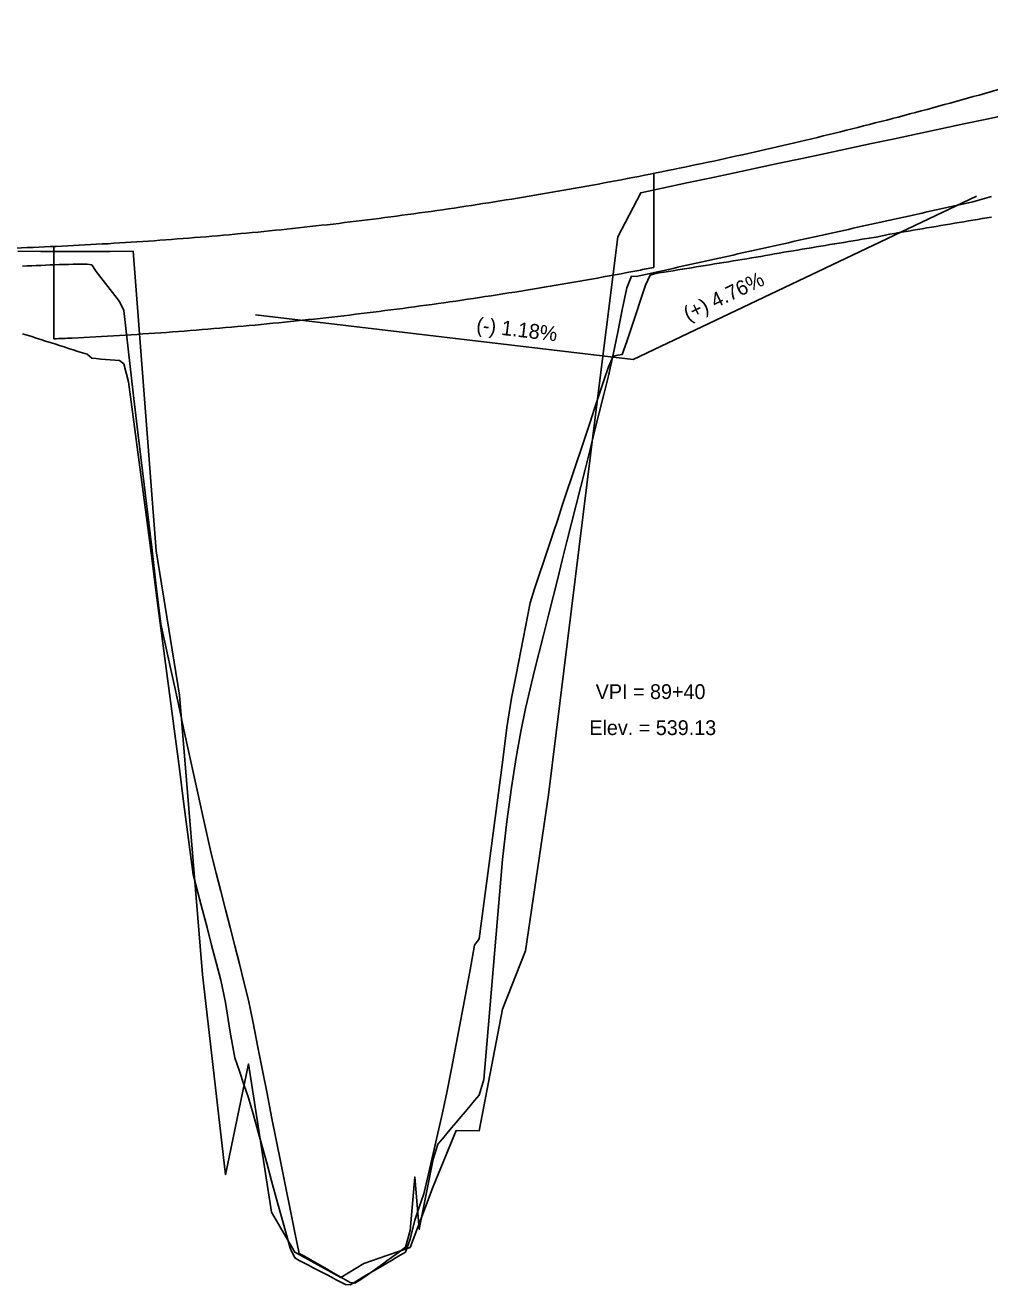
# Model space of a CAD drawing. Extents: x 1733822 to 1737718, y 1214897 to 1219897.
# Drawn here: x 1735400.6 to 1735609.6, y 1218087.6 to 1218360.6 of the extents above; entities that cross this region are included whole.
import ezdxf

# ---------------------------------------------------------------- set-up
doc = ezdxf.new("R2010")
doc.units = 0
for name, color, linetype in [('RD_DDB_GradeTX', 7, 'Continuous'), ('RD_DDB_Profile_EX', 7, 'Continuous'), ('RD_DDB_Profile_Lbl', 7, 'Continuous'), ('RD_DDB_Profile_PR', 7, 'Continuous'), ('RD_PD_Bridge', 7, 'Continuous'), ('RD_Sketch1', 7, 'Continuous'), ('RD_Sketch2', 7, 'Continuous')]:
    doc.layers.add(name, color=color, linetype=linetype)

msp = doc.modelspace()

# ---------------------------------------------------------------- linework, layer by layer
at = {"layer": 'RD_DDB_GradeTX'}
for p in [(1735606.71, 1218323.5), (1735450.48, 1218297.76)]:
    msp.add_line(p, (1735532.31, 1218288.09), dxfattribs=at)
at = {"layer": 'RD_DDB_Profile_EX'}
for points in [[(1735413.97, 1218311.54), (1735418.97, 1218311.53), (1735423.97, 1218311.57), (1735428.97, 1218246.61), (1735433.97, 1218215.39), (1735438.97, 1218154.8), (1735443.97, 1218111.43), (1735448.97, 1218135.45), (1735453.97, 1218103.33), (1735458.97, 1218094.65), (1735463.97, 1218091.91), (1735468.97, 1218089.16), (1735473.97, 1218092.22), (1735478.97, 1218093.96), (1735483.97, 1218095.69), (1735488.97, 1218108.91), (1735493.97, 1218121.02), (1735498.97, 1218120.99), (1735503.97, 1218147.3), (1735508.97, 1218159.95), (1735513.97, 1218193.75), (1735518.97, 1218234.06), (1735523.97, 1218274.37), (1735528.97, 1218314.68), (1735533.97, 1218324.23), (1735538.97, 1218325.29), (1735543.97, 1218326.36), (1735548.97, 1218327.42), (1735553.97, 1218328.49), (1735558.97, 1218329.55), (1735563.97, 1218330.62), (1735568.97, 1218331.69), (1735573.97, 1218332.75), (1735578.97, 1218333.82), (1735583.97, 1218334.88), (1735588.97, 1218335.95), (1735593.97, 1218337.02), (1735598.97, 1218338.08), (1735603.97, 1218339.15), (1735608.97, 1218340.21), (1735613.97, 1218341.28)], [(1735398.97, 1218311.55), (1735403.97, 1218311.54), (1735408.97, 1218311.54), (1735413.97, 1218311.54)]]:
    msp.add_lwpolyline(points, dxfattribs=at)
at = {"layer": 'RD_DDB_Profile_PR'}
msp.add_spline([(1735269.77, 1218317.64), (1735279.77, 1218316.52), (1735289.77, 1218315.51), (1735299.77, 1218314.63), (1735309.77, 1218313.86), (1735319.77, 1218313.22), (1735329.77, 1218312.69), (1735339.77, 1218312.28), (1735349.77, 1218311.99), (1735359.77, 1218311.81), (1735369.77, 1218311.76), (1735379.77, 1218311.83), (1735389.77, 1218312.01), (1735399.77, 1218312.31), (1735409.77, 1218312.74), (1735419.77, 1218313.28), (1735429.77, 1218313.94), (1735439.77, 1218314.72), (1735449.77, 1218315.61), (1735459.77, 1218316.63), (1735469.77, 1218317.76), (1735479.77, 1218319.02), (1735489.77, 1218320.39), (1735499.77, 1218321.88), (1735509.77, 1218323.49), (1735519.77, 1218325.22), (1735529.77, 1218327.07), (1735539.77, 1218329.04), (1735549.77, 1218331.12), (1735559.77, 1218333.33), (1735569.77, 1218335.65), (1735579.77, 1218338.09), (1735589.77, 1218340.65), (1735599.77, 1218343.33), (1735609.77, 1218346.13), (1735619.77, 1218349.05), (1735629.77, 1218352.08), (1735639.77, 1218355.24), (1735649.77, 1218358.51), (1735659.77, 1218361.9), (1735669.77, 1218365.41), (1735679.77, 1218369.04), (1735689.77, 1218372.79), (1735699.77, 1218376.66), (1735709.77, 1218380.65), (1735719.77, 1218384.75), (1735729.77, 1218388.98), (1735739.77, 1218393.32), (1735749.77, 1218397.78), (1735759.77, 1218402.36), (1735769.77, 1218407.06)], degree=3, dxfattribs=at)
at = {"layer": 'RD_PD_Bridge'}
for p, q in [((1735536.77, 1218308.05), (1735536.77, 1218328.43)), ((1735406.77, 1218292.58), (1735406.77, 1218312.6))]:
    msp.add_line(p, q, dxfattribs=at)
msp.add_spline([(1735406.77, 1218292.58), (1735410.73, 1218292.76), (1735420.97, 1218293.31), (1735431.2, 1218293.99), (1735441.44, 1218294.79), (1735451.67, 1218295.7), (1735461.91, 1218296.74), (1735472.14, 1218297.9), (1735482.37, 1218299.19), (1735492.6, 1218300.59), (1735502.83, 1218302.12), (1735513.06, 1218303.76), (1735523.29, 1218305.53), (1735533.52, 1218307.42), (1735536.77, 1218308.05)], degree=3, dxfattribs=at)
at = {"layer": 'RD_Sketch1'}
for points in [[(1735515.97, 1218253.45), (1735516.97, 1218256.46), (1735517.97, 1218259.47), (1735518.97, 1218262.48), (1735519.97, 1218265.49), (1735520.97, 1218268.49), (1735521.97, 1218271.5), (1735522.97, 1218274.51), (1735523.97, 1218277.52), (1735524.97, 1218280.53), (1735525.97, 1218283.53), (1735526.97, 1218286.54), (1735527.97, 1218288.85), (1735528.97, 1218289.02), (1735529.97, 1218289.19), (1735530.97, 1218291.98), (1735531.97, 1218295.04), (1735532.97, 1218298.1), (1735533.97, 1218301.17), (1735534.97, 1218304.23), (1735535.97, 1218306.35), (1735536.97, 1218306.67), (1735537.97, 1218306.86), (1735538.97, 1218307.02), (1735539.97, 1218307.19), (1735540.97, 1218307.35), (1735541.97, 1218307.51), (1735542.97, 1218307.67), (1735543.97, 1218307.84), (1735544.97, 1218308), (1735545.97, 1218308.16), (1735546.97, 1218308.32), (1735547.97, 1218308.49), (1735548.97, 1218308.65), (1735549.97, 1218308.81), (1735550.97, 1218308.97), (1735551.97, 1218309.14), (1735552.97, 1218309.3), (1735553.97, 1218309.46), (1735554.97, 1218309.62), (1735555.97, 1218309.79), (1735556.97, 1218309.95), (1735557.97, 1218310.11), (1735558.97, 1218310.28), (1735559.97, 1218310.44), (1735560.97, 1218310.61), (1735561.97, 1218310.82), (1735562.97, 1218311), (1735563.97, 1218311.17), (1735564.97, 1218311.33), (1735565.97, 1218311.5), (1735566.97, 1218311.66), (1735567.97, 1218311.83), (1735568.97, 1218312), (1735569.97, 1218312.16), (1735570.97, 1218312.33), (1735571.97, 1218312.49), (1735572.97, 1218312.66), (1735573.97, 1218312.82), (1735574.97, 1218312.99), (1735575.97, 1218313.15), (1735576.97, 1218313.32), (1735577.97, 1218313.49), (1735578.97, 1218313.65), (1735579.97, 1218313.82), (1735580.97, 1218313.98), (1735581.97, 1218314.15), (1735582.97, 1218314.31), (1735583.97, 1218314.48), (1735584.97, 1218314.65), (1735585.97, 1218314.84), (1735586.97, 1218315.04), (1735587.97, 1218315.25), (1735588.97, 1218315.44), (1735589.97, 1218315.61), (1735590.97, 1218315.78), (1735591.97, 1218315.94), (1735592.97, 1218316.11), (1735593.97, 1218316.28), (1735594.97, 1218316.45), (1735595.97, 1218316.62), (1735596.97, 1218316.78), (1735597.97, 1218316.95), (1735598.97, 1218317.12), (1735599.97, 1218317.29), (1735600.97, 1218317.46), (1735601.97, 1218317.63), (1735602.97, 1218317.79), (1735603.97, 1218317.96), (1735604.97, 1218318.13), (1735605.97, 1218318.3), (1735606.97, 1218318.47), (1735607.97, 1218318.63), (1735608.97, 1218318.8), (1735609.97, 1218318.97)], [(1735399.97, 1218293.7), (1735400.97, 1218293.38), (1735401.97, 1218293.06), (1735402.97, 1218292.74), (1735403.97, 1218292.42), (1735404.97, 1218292.1), (1735405.97, 1218291.78), (1735406.97, 1218291.47), (1735407.97, 1218291.15), (1735408.97, 1218290.83), (1735409.97, 1218290.51), (1735410.97, 1218290.19), (1735411.97, 1218289.87), (1735412.97, 1218289.55), (1735413.97, 1218289.23), (1735414.97, 1218288.38), (1735415.97, 1218288.29)], [(1735415.97, 1218288.29), (1735416.97, 1218288.21), (1735417.97, 1218288.12), (1735418.97, 1218288.04), (1735419.97, 1218287.96), (1735420.97, 1218287.87), (1735421.97, 1218287.16), (1735422.97, 1218283.3), (1735423.97, 1218275.67), (1735424.97, 1218268.04), (1735425.97, 1218260.41), (1735426.97, 1218252.78), (1735427.97, 1218245.15), (1735428.97, 1218237.52), (1735429.97, 1218229.89), (1735430.97, 1218222.26), (1735431.97, 1218214.63), (1735432.97, 1218207), (1735433.97, 1218199.37), (1735434.97, 1218191.74), (1735435.97, 1218184.11), (1735436.97, 1218176.48), (1735437.97, 1218172.57), (1735438.97, 1218168.78), (1735439.97, 1218164.99), (1735440.97, 1218161.19), (1735441.97, 1218157.4), (1735442.97, 1218153.61), (1735443.97, 1218148.73), (1735444.97, 1218142.37), (1735445.97, 1218136.76), (1735446.97, 1218133.89), (1735447.97, 1218131.01), (1735448.97, 1218128.14), (1735449.97, 1218124.63), (1735450.97, 1218120.99), (1735451.97, 1218117.36), (1735452.97, 1218113.72), (1735453.97, 1218110.09), (1735454.97, 1218106.46), (1735455.97, 1218102.82), (1735456.97, 1218099.19), (1735457.97, 1218095.55), (1735458.97, 1218093.4), (1735459.97, 1218092.87), (1735460.97, 1218092.34), (1735461.97, 1218091.82), (1735462.97, 1218091.3), (1735463.97, 1218090.78), (1735464.97, 1218090.26), (1735465.97, 1218089.74), (1735466.97, 1218089.22), (1735467.97, 1218088.7), (1735468.97, 1218088.18), (1735469.97, 1218087.66), (1735470.97, 1218087.59), (1735471.97, 1218088.18), (1735472.97, 1218088.77), (1735473.97, 1218089.36), (1735474.97, 1218089.94), (1735475.97, 1218090.53), (1735476.97, 1218091.12), (1735477.97, 1218091.71), (1735478.97, 1218092.3), (1735479.97, 1218092.89), (1735480.97, 1218093.48), (1735481.97, 1218094.07), (1735482.97, 1218094.67), (1735483.97, 1218097.45), (1735484.97, 1218101.59), (1735485.97, 1218104.43), (1735486.97, 1218107.27), (1735487.97, 1218111.66), (1735488.97, 1218116.06), (1735489.97, 1218120.45), (1735490.97, 1218124.85), (1735491.97, 1218129.24), (1735492.97, 1218134.4), (1735493.97, 1218139.75), (1735494.97, 1218145.11), (1735495.97, 1218150.46), (1735496.97, 1218155.82), (1735497.97, 1218161.18), (1735498.97, 1218162.56), (1735499.97, 1218170.19), (1735500.97, 1218177.83), (1735501.97, 1218185.47), (1735502.97, 1218193.11), (1735503.97, 1218200.74), (1735504.97, 1218208.38), (1735505.97, 1218214.73), (1735506.97, 1218219.78), (1735507.97, 1218224.97), (1735508.97, 1218230.16), (1735509.97, 1218235.35), (1735510.97, 1218238.41), (1735511.97, 1218241.42), (1735512.97, 1218244.43), (1735513.97, 1218247.44), (1735514.97, 1218250.45), (1735515.97, 1218253.45)]]:
    msp.add_lwpolyline(points, dxfattribs=at)
at = {"layer": 'RD_Sketch2'}
for points in [[(1735513.97, 1218232.67), (1735514.97, 1218236.66), (1735515.97, 1218240.65), (1735516.97, 1218244.64), (1735517.97, 1218248.63), (1735518.97, 1218252.62), (1735519.97, 1218256.61), (1735520.97, 1218260.6), (1735521.97, 1218264.59), (1735522.97, 1218268.58), (1735523.97, 1218272.56), (1735524.97, 1218276.55), (1735525.97, 1218280.54), (1735526.97, 1218284.53), (1735527.97, 1218289.18), (1735528.97, 1218294.01), (1735529.97, 1218298.84), (1735530.97, 1218303.67), (1735531.97, 1218306.16), (1735532.97, 1218306.07), (1735533.97, 1218306.29), (1735534.97, 1218306.52), (1735535.97, 1218306.74), (1735536.97, 1218306.96), (1735537.97, 1218307.19), (1735538.97, 1218307.41), (1735539.97, 1218307.63), (1735540.97, 1218307.85), (1735541.97, 1218308.08), (1735542.97, 1218308.3), (1735543.97, 1218308.52), (1735544.97, 1218308.75), (1735545.97, 1218308.97), (1735546.97, 1218309.19), (1735547.97, 1218309.42), (1735548.97, 1218309.64), (1735549.97, 1218309.86), (1735550.97, 1218310.09), (1735551.97, 1218310.31), (1735552.97, 1218310.53), (1735553.97, 1218310.75), (1735554.97, 1218310.98), (1735555.97, 1218311.2), (1735556.97, 1218311.42), (1735557.97, 1218311.63), (1735558.97, 1218311.85), (1735559.97, 1218312.08), (1735560.97, 1218312.3), (1735561.97, 1218312.52), (1735562.97, 1218312.74), (1735563.97, 1218312.97), (1735564.97, 1218313.19), (1735565.97, 1218313.41), (1735566.97, 1218313.64), (1735567.97, 1218313.86), (1735568.97, 1218314.08), (1735569.97, 1218314.3), (1735570.97, 1218314.53), (1735571.97, 1218314.75), (1735572.97, 1218314.97), (1735573.97, 1218315.2), (1735574.97, 1218315.42), (1735575.97, 1218315.64), (1735576.97, 1218315.86), (1735577.97, 1218316.09), (1735578.97, 1218316.31), (1735579.97, 1218316.53), (1735580.97, 1218316.76), (1735581.97, 1218316.97), (1735582.97, 1218317.19), (1735583.97, 1218317.4), (1735584.97, 1218317.63), (1735585.97, 1218317.85), (1735586.97, 1218318.07), (1735587.97, 1218318.29), (1735588.97, 1218318.52), (1735589.97, 1218318.74), (1735590.97, 1218318.96), (1735591.97, 1218319.18), (1735592.97, 1218319.41), (1735593.97, 1218319.63), (1735594.97, 1218319.85), (1735595.97, 1218320.07), (1735596.97, 1218320.3), (1735597.97, 1218320.52), (1735598.97, 1218320.74), (1735599.97, 1218320.96), (1735600.97, 1218321.19), (1735601.97, 1218321.41), (1735602.97, 1218321.63), (1735603.97, 1218321.85), (1735604.97, 1218322.08), (1735605.97, 1218322.3), (1735606.97, 1218322.56), (1735607.97, 1218322.85), (1735608.97, 1218323.13), (1735609.97, 1218323.42)], [(1735399.97, 1218308.34), (1735400.97, 1218308.38), (1735401.97, 1218308.42), (1735402.97, 1218308.46), (1735403.97, 1218308.51), (1735404.97, 1218308.55), (1735405.97, 1218308.59), (1735406.97, 1218308.64), (1735407.97, 1218308.68), (1735408.97, 1218308.71), (1735409.97, 1218308.72), (1735410.97, 1218308.73), (1735411.97, 1218308.74), (1735412.97, 1218308.75), (1735413.97, 1218308.76)], [(1735413.97, 1218308.76), (1735414.97, 1218308.63), (1735415.97, 1218307.17), (1735416.97, 1218305.85), (1735417.97, 1218304.56), (1735418.97, 1218303.27), (1735419.97, 1218301.98), (1735420.97, 1218300.69), (1735421.97, 1218298.69), (1735422.97, 1218289.78), (1735423.97, 1218280.86), (1735424.97, 1218272.26), (1735425.97, 1218263.95), (1735426.97, 1218255.64), (1735427.97, 1218247.33), (1735428.97, 1218239.02), (1735429.97, 1218230.75), (1735430.97, 1218226.17), (1735431.97, 1218221.59), (1735432.97, 1218217.01), (1735433.97, 1218212.43), (1735434.97, 1218207.85), (1735435.97, 1218203.27), (1735436.97, 1218198.69), (1735437.97, 1218194.11), (1735438.97, 1218189.53), (1735439.97, 1218184.95), (1735440.97, 1218180.73), (1735441.97, 1218176.8), (1735442.97, 1218172.87), (1735443.97, 1218168.93), (1735444.97, 1218165), (1735445.97, 1218161.07), (1735446.97, 1218157.14), (1735447.97, 1218153.21), (1735448.97, 1218149.27), (1735449.97, 1218144.39), (1735450.97, 1218139.08), (1735451.97, 1218134.06), (1735452.97, 1218129.04), (1735453.97, 1218124.02), (1735454.97, 1218119), (1735455.97, 1218113.99), (1735456.97, 1218108.97), (1735457.97, 1218103.95), (1735458.97, 1218098.93), (1735459.97, 1218094.38), (1735460.97, 1218093.84), (1735461.97, 1218093.3), (1735462.97, 1218092.73), (1735463.97, 1218092.15), (1735464.97, 1218091.58), (1735465.97, 1218091), (1735466.97, 1218090.43), (1735467.97, 1218089.85), (1735468.97, 1218089.27), (1735469.97, 1218088.7), (1735470.97, 1218088.12), (1735471.97, 1218087.97), (1735472.97, 1218088.55), (1735473.97, 1218089.14), (1735474.97, 1218089.87), (1735475.97, 1218090.6), (1735476.97, 1218091.33), (1735477.97, 1218092.06), (1735478.97, 1218092.79), (1735479.97, 1218093.52), (1735480.97, 1218094.25), (1735481.97, 1218094.98), (1735482.97, 1218095.71), (1735483.97, 1218099.37), (1735484.97, 1218110.98), (1735485.97, 1218099.62), (1735486.97, 1218104.68), (1735487.97, 1218109.75), (1735488.97, 1218114.81), (1735489.97, 1218118.03), (1735490.97, 1218119.22), (1735491.97, 1218120.41), (1735492.97, 1218121.6), (1735493.97, 1218122.78), (1735494.97, 1218123.97), (1735495.97, 1218125.16), (1735496.97, 1218126.35), (1735497.97, 1218127.54), (1735498.97, 1218128.72), (1735499.97, 1218132.07), (1735500.97, 1218143.99), (1735501.97, 1218155.9), (1735502.97, 1218167.82), (1735503.97, 1218179.74), (1735504.97, 1218188), (1735505.97, 1218195.37), (1735506.97, 1218201.85), (1735507.97, 1218207.49), (1735508.97, 1218212.49), (1735509.97, 1218216.72), (1735510.97, 1218220.71), (1735511.97, 1218224.69), (1735512.97, 1218228.68), (1735513.97, 1218232.67)]]:
    msp.add_lwpolyline(points, dxfattribs=at)

# ---------------------------------------------------------------- texts
at = {"layer": 'RD_DDB_GradeTX'}
for s, rotation, p in [('(+) 4.76%', 25.4482, (1735544.2, 1218296.36)), ('(-) 1.18%', 353.2596, (1735498.21, 1218294.09))]:
    msp.add_text(s, height=3.2, rotation=rotation, dxfattribs=at).set_placement(p)
at = {"layer": 'RD_DDB_Profile_Lbl'}
for s, p in [('VPI = 89+40', (1735524.2, 1218214.53)), ('Elev. = 539.13', (1735522.83, 1218206.72))]:
    msp.add_text(s, height=3.2, dxfattribs=at).set_placement(p)

doc.saveas('drawing.dxf')
